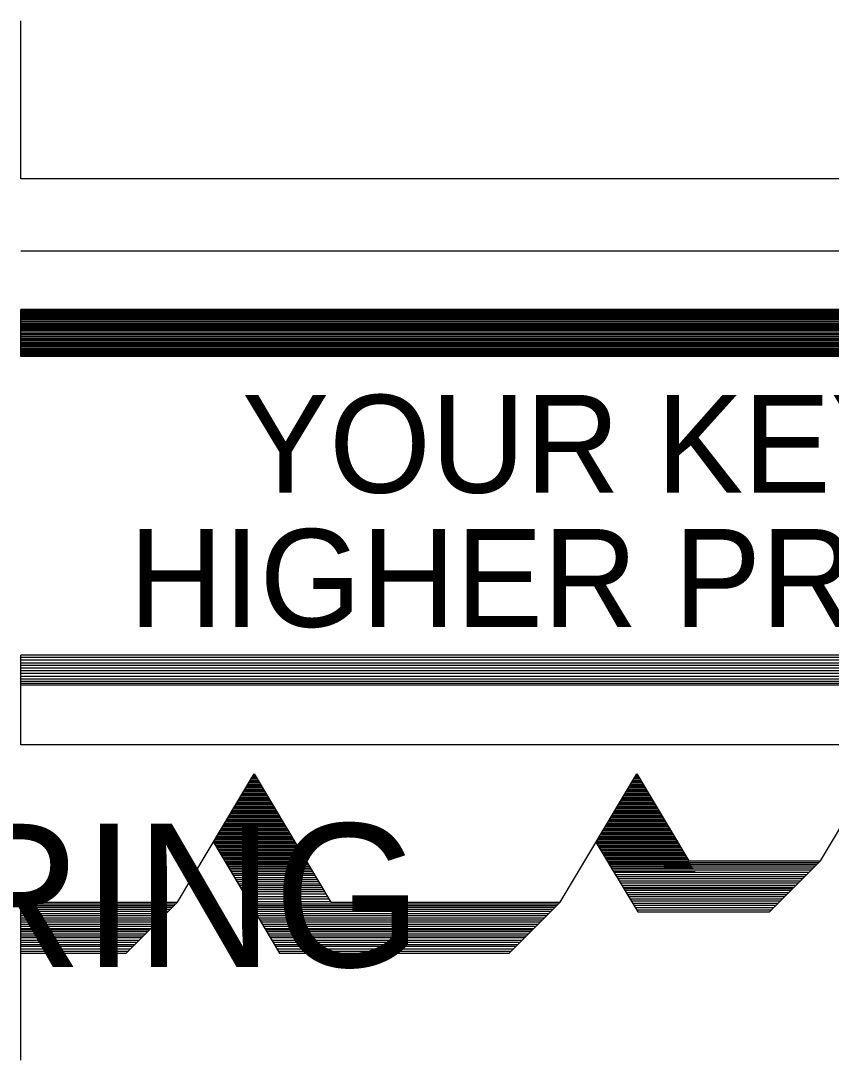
# Model space of a CAD drawing. Extents: x 22388.1 to 22405.7, y 22369.6 to 22390.4.
# Drawn here: x 22389.095 to 22389.2819, y 22369.983 to 22370.2226 of the extents above; entities that cross this region are included whole.
import ezdxf

# ---------------------------------------------------------------- set-up
doc = ezdxf.new("R2010")
doc.units = 0
for name, color, linetype in [('Level 1', 7, 'Continuous'), ('Level 10', 7, 'Continuous'), ('Level 2', 7, 'Continuous'), ('Level 7', 7, 'Continuous')]:
    doc.layers.add(name, color=color, linetype=linetype)

msp = doc.modelspace()

# ---------------------------------------------------------------- linework, layer by layer
at = {"layer": 'Level 1'}
msp.add_line((22389.095, 22370.1452), (22389.095, 22370.15608), dxfattribs=at)
at = {"layer": 'Level 10'}
msp.add_line((22389.4555, 22370.16949), (22389.095, 22370.16949), dxfattribs=at)
at = {"layer": 'Level 2'}
for p, q in [((22389.4717, 22370.15608), (22389.095, 22370.15608)), ((22389.47204, 22370.15583), (22389.095, 22370.15583)), ((22389.47233, 22370.15558), (22389.095, 22370.15558)), ((22389.47266, 22370.15529), (22389.095, 22370.15529)), ((22389.47304, 22370.15499), (22389.095, 22370.15499)), ((22389.47337, 22370.1547), (22389.095, 22370.1547)), ((22389.47379, 22370.15437), (22389.095, 22370.15437)), ((22389.47412, 22370.15408), (22389.095, 22370.15408)), ((22389.47454, 22370.15374), (22389.095, 22370.15374)), ((22389.47495, 22370.15341), (22389.095, 22370.15341)), ((22389.47529, 22370.15312), (22389.095, 22370.15312)), ((22389.47566, 22370.15279), (22389.095, 22370.15279)), ((22389.47612, 22370.15245), (22389.095, 22370.15245)), ((22389.47645, 22370.15216), (22389.095, 22370.15216)), ((22389.47679, 22370.15187), (22389.095, 22370.15187)), ((22389.4772, 22370.15154), (22389.095, 22370.15154)), ((22389.47762, 22370.1512), (22389.095, 22370.1512)), ((22389.478, 22370.15087), (22389.095, 22370.15087)), ((22389.47845, 22370.15049), (22389.095, 22370.15049)), ((22389.47883, 22370.1502), (22389.095, 22370.1502)), ((22389.4792, 22370.14987), (22389.095, 22370.14987)), ((22389.47966, 22370.14949), (22389.095, 22370.14949)), ((22389.48008, 22370.14916), (22389.095, 22370.14916)), ((22389.48037, 22370.14891), (22389.095, 22370.14891)), ((22389.48079, 22370.14858), (22389.095, 22370.14858)), ((22389.48116, 22370.14824), (22389.095, 22370.14824)), ((22389.48154, 22370.14795), (22389.095, 22370.14795)), ((22389.48187, 22370.14766), (22389.095, 22370.14766)), ((22389.4822, 22370.14741), (22389.095, 22370.14741)), ((22389.48266, 22370.14704), (22389.095, 22370.14704)), ((22389.48295, 22370.14679), (22389.095, 22370.14679)), ((22389.48329, 22370.14649), (22389.095, 22370.14649)), ((22389.48358, 22370.14624), (22389.095, 22370.14624)), ((22389.48391, 22370.14599), (22389.095, 22370.14599)), ((22389.48416, 22370.14579), (22389.095, 22370.14579)), ((22389.48445, 22370.14554), (22389.095, 22370.14554)), ((22389.48466, 22370.14537), (22389.095, 22370.14537)), ((22389.48487, 22370.1452), (22389.095, 22370.1452)), ((22389.50416, 22370.07637), (22389.095, 22370.07637)), ((22389.095, 22370.0557), (22389.095, 22370.07637)), ((22389.5035, 22370.07583), (22389.095, 22370.07583)), ((22389.50279, 22370.07524), (22389.095, 22370.07524)), ((22389.502, 22370.07458), (22389.095, 22370.07458)), ((22389.50133, 22370.07404), (22389.095, 22370.07404)), ((22389.50054, 22370.07337), (22389.095, 22370.07337)), ((22389.49983, 22370.07279), (22389.095, 22370.07279)), ((22389.49908, 22370.07216), (22389.095, 22370.07216)), ((22389.49825, 22370.07149), (22389.095, 22370.07149)), ((22389.4975, 22370.07087), (22389.095, 22370.07087)), ((22389.49679, 22370.07029), (22389.095, 22370.07029)), ((22389.49629, 22370.06987), (22389.095, 22370.06987)), ((22389.49583, 22370.06949), (22389.095, 22370.06949)), ((22389.47916, 22370.0557), (22389.095, 22370.0557)), ((22389.14758, 22370.04695), (22389.15008, 22370.04695)), ((22389.14779, 22370.04729), (22389.14987, 22370.04729)), ((22389.148, 22370.04762), (22389.14966, 22370.04762)), ((22389.14816, 22370.04795), (22389.1495, 22370.04795)), ((22389.14837, 22370.04829), (22389.14929, 22370.04829)), ((22389.14858, 22370.04862), (22389.14908, 22370.04862)), ((22389.23583, 22370.04695), (22389.23833, 22370.04695)), ((22389.23604, 22370.04729), (22389.23812, 22370.04729)), ((22389.23625, 22370.04762), (22389.23791, 22370.04762)), ((22389.23641, 22370.04795), (22389.23775, 22370.04795)), ((22389.23658, 22370.0482), (22389.23758, 22370.0482)), ((22389.23675, 22370.04845), (22389.23741, 22370.04845)), ((22389.23687, 22370.0487), (22389.23729, 22370.0487)), ((22389.14616, 22370.04462), (22389.15145, 22370.04462)), ((22389.14637, 22370.04495), (22389.15129, 22370.04495)), ((22389.14658, 22370.04529), (22389.15108, 22370.04529)), ((22389.14679, 22370.04562), (22389.15087, 22370.04562)), ((22389.147, 22370.04595), (22389.15066, 22370.04595)), ((22389.14716, 22370.04629), (22389.15045, 22370.04629)), ((22389.14737, 22370.04662), (22389.15029, 22370.04662)), ((22389.23441, 22370.04462), (22389.2397, 22370.04462)), ((22389.23462, 22370.04495), (22389.23954, 22370.04495)), ((22389.23483, 22370.04529), (22389.23933, 22370.04529)), ((22389.23504, 22370.04562), (22389.23912, 22370.04562)), ((22389.23525, 22370.04595), (22389.23891, 22370.04595)), ((22389.23541, 22370.04629), (22389.2387, 22370.04629)), ((22389.23562, 22370.04662), (22389.23854, 22370.04662)), ((22389.14479, 22370.04229), (22389.15287, 22370.04229)), ((22389.145, 22370.04262), (22389.15266, 22370.04262)), ((22389.1452, 22370.04295), (22389.15245, 22370.04295)), ((22389.14541, 22370.04329), (22389.15229, 22370.04329)), ((22389.14562, 22370.04362), (22389.15208, 22370.04362)), ((22389.14583, 22370.04395), (22389.15187, 22370.04395)), ((22389.14604, 22370.04429), (22389.15166, 22370.04429)), ((22389.23304, 22370.04229), (22389.24112, 22370.04229)), ((22389.23325, 22370.04262), (22389.24091, 22370.04262)), ((22389.23345, 22370.04295), (22389.2407, 22370.04295)), ((22389.23366, 22370.04329), (22389.24054, 22370.04329)), ((22389.23387, 22370.04362), (22389.24033, 22370.04362)), ((22389.23408, 22370.04395), (22389.24012, 22370.04395)), ((22389.23429, 22370.04429), (22389.23991, 22370.04429)), ((22389.1432, 22370.03962), (22389.15445, 22370.03962)), ((22389.14337, 22370.03995), (22389.15425, 22370.03995)), ((22389.14358, 22370.04029), (22389.15408, 22370.04029)), ((22389.14379, 22370.04062), (22389.15387, 22370.04062)), ((22389.144, 22370.04095), (22389.15366, 22370.04095)), ((22389.1442, 22370.04129), (22389.15345, 22370.04129)), ((22389.14437, 22370.04162), (22389.15325, 22370.04162)), ((22389.14458, 22370.04195), (22389.15308, 22370.04195)), ((22389.23145, 22370.03962), (22389.2427, 22370.03962)), ((22389.23162, 22370.03995), (22389.2425, 22370.03995)), ((22389.23183, 22370.04029), (22389.24233, 22370.04029)), ((22389.23204, 22370.04062), (22389.24212, 22370.04062)), ((22389.23225, 22370.04095), (22389.24191, 22370.04095)), ((22389.23245, 22370.04129), (22389.2417, 22370.04129)), ((22389.23262, 22370.04162), (22389.2415, 22370.04162)), ((22389.23283, 22370.04195), (22389.24133, 22370.04195)), ((22389.14183, 22370.03729), (22389.15587, 22370.03729)), ((22389.14204, 22370.03762), (22389.15566, 22370.03762)), ((22389.14225, 22370.03795), (22389.15545, 22370.03795)), ((22389.14245, 22370.03829), (22389.15525, 22370.03829)), ((22389.14266, 22370.03862), (22389.15508, 22370.03862)), ((22389.14279, 22370.03895), (22389.15487, 22370.03895)), ((22389.143, 22370.03929), (22389.15466, 22370.03929)), ((22389.23008, 22370.03729), (22389.24412, 22370.03729)), ((22389.23029, 22370.03762), (22389.24391, 22370.03762)), ((22389.2305, 22370.03795), (22389.2437, 22370.03795)), ((22389.2307, 22370.03829), (22389.2435, 22370.03829)), ((22389.23091, 22370.03862), (22389.24333, 22370.03862)), ((22389.23104, 22370.03895), (22389.24312, 22370.03895)), ((22389.23125, 22370.03929), (22389.24291, 22370.03929)), ((22389.14037, 22370.03495), (22389.15725, 22370.03495)), ((22389.14058, 22370.03529), (22389.15704, 22370.03529)), ((22389.14079, 22370.03562), (22389.15687, 22370.03562)), ((22389.141, 22370.03595), (22389.15666, 22370.03595)), ((22389.1412, 22370.03629), (22389.15645, 22370.03629)), ((22389.14141, 22370.03662), (22389.15625, 22370.03662)), ((22389.14162, 22370.03695), (22389.15604, 22370.03695)), ((22389.22862, 22370.03495), (22389.2455, 22370.03495)), ((22389.22883, 22370.03529), (22389.24529, 22370.03529)), ((22389.22904, 22370.03562), (22389.24512, 22370.03562)), ((22389.22925, 22370.03595), (22389.24491, 22370.03595)), ((22389.22945, 22370.03629), (22389.2447, 22370.03629)), ((22389.22966, 22370.03662), (22389.2445, 22370.03662)), ((22389.22987, 22370.03695), (22389.24429, 22370.03695)), ((22389.13941, 22370.03329), (22389.1547, 22370.0077)), ((22389.13941, 22370.03329), (22389.15825, 22370.03329)), ((22389.13958, 22370.03362), (22389.15804, 22370.03362)), ((22389.13962, 22370.03295), (22389.15845, 22370.03295)), ((22389.13979, 22370.03395), (22389.15783, 22370.03395)), ((22389.13983, 22370.03262), (22389.15866, 22370.03262)), ((22389.14, 22370.03429), (22389.15766, 22370.03429)), ((22389.1402, 22370.03462), (22389.15745, 22370.03462)), ((22389.22766, 22370.03329), (22389.23733, 22370.0172)), ((22389.22766, 22370.03329), (22389.2465, 22370.03329)), ((22389.22783, 22370.03362), (22389.24629, 22370.03362)), ((22389.22787, 22370.03295), (22389.2467, 22370.03295)), ((22389.22804, 22370.03395), (22389.24608, 22370.03395)), ((22389.22808, 22370.03262), (22389.24691, 22370.03262)), ((22389.22825, 22370.03429), (22389.24591, 22370.03429)), ((22389.22845, 22370.03462), (22389.2457, 22370.03462)), ((22389.14, 22370.03229), (22389.15883, 22370.03229)), ((22389.1402, 22370.03195), (22389.15904, 22370.03195)), ((22389.14041, 22370.03162), (22389.15916, 22370.03162)), ((22389.14062, 22370.03129), (22389.15937, 22370.03129)), ((22389.14079, 22370.03095), (22389.15958, 22370.03095)), ((22389.141, 22370.03062), (22389.15979, 22370.03062)), ((22389.1412, 22370.03029), (22389.16, 22370.03029)), ((22389.22825, 22370.03229), (22389.24708, 22370.03229)), ((22389.22845, 22370.03195), (22389.24729, 22370.03195)), ((22389.22866, 22370.03162), (22389.24741, 22370.03162)), ((22389.22887, 22370.03129), (22389.24762, 22370.03129)), ((22389.22904, 22370.03095), (22389.24783, 22370.03095)), ((22389.22925, 22370.03062), (22389.24804, 22370.03062)), ((22389.22945, 22370.03029), (22389.24825, 22370.03029)), ((22389.14141, 22370.02995), (22389.1602, 22370.02995)), ((22389.14162, 22370.02962), (22389.16041, 22370.02962)), ((22389.14179, 22370.02929), (22389.16062, 22370.02929)), ((22389.142, 22370.02895), (22389.16083, 22370.02895)), ((22389.1422, 22370.02862), (22389.16104, 22370.02862)), ((22389.14237, 22370.02837), (22389.1612, 22370.02837)), ((22389.14254, 22370.02804), (22389.16137, 22370.02804)), ((22389.14275, 22370.0277), (22389.16158, 22370.0277)), ((22389.22966, 22370.02995), (22389.24845, 22370.02995)), ((22389.22987, 22370.02962), (22389.24866, 22370.02962)), ((22389.23004, 22370.02929), (22389.24887, 22370.02929)), ((22389.23025, 22370.02895), (22389.24908, 22370.02895)), ((22389.23045, 22370.02862), (22389.24929, 22370.02862)), ((22389.23062, 22370.02837), (22389.24945, 22370.02837)), ((22389.23079, 22370.02804), (22389.24962, 22370.02804)), ((22389.231, 22370.0277), (22389.24983, 22370.0277)), ((22389.24333, 22370.02858), (22389.27904, 22370.02858)), ((22389.24333, 22370.0282), (22389.27866, 22370.0282)), ((22389.24333, 22370.02783), (22389.27829, 22370.02783)), ((22389.26766, 22370.0172), (22389.27945, 22370.02899)), ((22389.14295, 22370.02733), (22389.16183, 22370.02733)), ((22389.1432, 22370.02691), (22389.16208, 22370.02691)), ((22389.14345, 22370.02654), (22389.16229, 22370.02654)), ((22389.1437, 22370.02608), (22389.16258, 22370.02608)), ((22389.14395, 22370.02566), (22389.16279, 22370.02566)), ((22389.2312, 22370.02733), (22389.25008, 22370.02733)), ((22389.23145, 22370.02691), (22389.25033, 22370.02691)), ((22389.2317, 22370.02654), (22389.25054, 22370.02654)), ((22389.23183, 22370.02637), (22389.27683, 22370.02637)), ((22389.23212, 22370.02587), (22389.27633, 22370.02587)), ((22389.23241, 22370.02537), (22389.27583, 22370.02537)), ((22389.24333, 22370.02737), (22389.27783, 22370.02737)), ((22389.24333, 22370.02691), (22389.27737, 22370.02691)), ((22389.14429, 22370.02516), (22389.16312, 22370.02516)), ((22389.14454, 22370.0247), (22389.16337, 22370.0247)), ((22389.14483, 22370.0242), (22389.16366, 22370.0242)), ((22389.14512, 22370.0237), (22389.164, 22370.0237)), ((22389.14537, 22370.02329), (22389.16425, 22370.02329)), ((22389.14562, 22370.02287), (22389.1645, 22370.02287)), ((22389.2327, 22370.02491), (22389.27537, 22370.02491)), ((22389.233, 22370.02441), (22389.27487, 22370.02441)), ((22389.23329, 22370.02391), (22389.27437, 22370.02391)), ((22389.23358, 22370.02341), (22389.27387, 22370.02341)), ((22389.23391, 22370.02291), (22389.27337, 22370.02291)), ((22389.14595, 22370.02237), (22389.16479, 22370.02237)), ((22389.1462, 22370.02191), (22389.16504, 22370.02191)), ((22389.1465, 22370.02141), (22389.16533, 22370.02141)), ((22389.14691, 22370.02074), (22389.16575, 22370.02074)), ((22389.23408, 22370.02258), (22389.27304, 22370.02258)), ((22389.23433, 22370.0222), (22389.27266, 22370.0222)), ((22389.23462, 22370.0217), (22389.27216, 22370.0217)), ((22389.23491, 22370.0212), (22389.27166, 22370.0212)), ((22389.23516, 22370.02079), (22389.27125, 22370.02079)), ((22389.095, 22370.01908), (22389.1307, 22370.01908)), ((22389.095, 22370.0187), (22389.13033, 22370.0187)), ((22389.095, 22370.01833), (22389.12995, 22370.01833)), ((22389.11933, 22370.0077), (22389.13112, 22370.01949)), ((22389.14725, 22370.0202), (22389.16608, 22370.0202)), ((22389.14758, 22370.01962), (22389.16641, 22370.01962)), ((22389.14791, 22370.01908), (22389.219, 22370.01908)), ((22389.14812, 22370.0187), (22389.21862, 22370.0187)), ((22389.14837, 22370.01833), (22389.21825, 22370.01833)), ((22389.20762, 22370.0077), (22389.21941, 22370.01949)), ((22389.2355, 22370.02024), (22389.2707, 22370.02024)), ((22389.23579, 22370.01974), (22389.2702, 22370.01974)), ((22389.23612, 22370.01924), (22389.2697, 22370.01924)), ((22389.23637, 22370.01879), (22389.26925, 22370.01879)), ((22389.23675, 22370.0182), (22389.26866, 22370.0182)), ((22389.095, 22370.01787), (22389.1295, 22370.01787)), ((22389.095, 22370.01741), (22389.12904, 22370.01741)), ((22389.095, 22370.01687), (22389.1285, 22370.01687)), ((22389.095, 22370.01637), (22389.128, 22370.01637)), ((22389.095, 22370.01587), (22389.1275, 22370.01587)), ((22389.14862, 22370.01787), (22389.21779, 22370.01787)), ((22389.14891, 22370.01741), (22389.21733, 22370.01741)), ((22389.14925, 22370.01687), (22389.21679, 22370.01687)), ((22389.14954, 22370.01637), (22389.21629, 22370.01637)), ((22389.14983, 22370.01587), (22389.21579, 22370.01587)), ((22389.23704, 22370.0177), (22389.26816, 22370.0177)), ((22389.23733, 22370.0172), (22389.26766, 22370.0172)), ((22389.095, 22370.01541), (22389.12704, 22370.01541)), ((22389.095, 22370.01491), (22389.12654, 22370.01491)), ((22389.095, 22370.01441), (22389.12604, 22370.01441)), ((22389.095, 22370.01391), (22389.12554, 22370.01391)), ((22389.095, 22370.01341), (22389.12504, 22370.01341)), ((22389.15008, 22370.01541), (22389.21533, 22370.01541)), ((22389.15041, 22370.01491), (22389.21483, 22370.01491)), ((22389.1507, 22370.01441), (22389.21433, 22370.01441)), ((22389.151, 22370.01391), (22389.21383, 22370.01391)), ((22389.15129, 22370.01341), (22389.21333, 22370.01341)), ((22389.095, 22370.01308), (22389.1247, 22370.01308)), ((22389.095, 22370.0127), (22389.12433, 22370.0127)), ((22389.095, 22370.0122), (22389.12383, 22370.0122)), ((22389.095, 22370.0117), (22389.12333, 22370.0117)), ((22389.095, 22370.01129), (22389.12291, 22370.01129)), ((22389.1515, 22370.01308), (22389.213, 22370.01308)), ((22389.1517, 22370.0127), (22389.21262, 22370.0127)), ((22389.152, 22370.0122), (22389.21212, 22370.0122)), ((22389.15233, 22370.0117), (22389.21162, 22370.0117)), ((22389.15258, 22370.01129), (22389.2112, 22370.01129)), ((22389.095, 22370.01074), (22389.12237, 22370.01074)), ((22389.095, 22370.01024), (22389.12187, 22370.01024)), ((22389.095, 22370.00974), (22389.12137, 22370.00974)), ((22389.095, 22370.00929), (22389.12091, 22370.00929)), ((22389.095, 22370.0087), (22389.12033, 22370.0087)), ((22389.15287, 22370.01074), (22389.21066, 22370.01074)), ((22389.1532, 22370.01024), (22389.21016, 22370.01024)), ((22389.1535, 22370.00974), (22389.20966, 22370.00974)), ((22389.15375, 22370.00929), (22389.2092, 22370.00929)), ((22389.15412, 22370.0087), (22389.20862, 22370.0087)), ((22389.095, 22370.0082), (22389.11983, 22370.0082)), ((22389.095, 22370.0077), (22389.11933, 22370.0077)), ((22389.15441, 22370.0082), (22389.20812, 22370.0082)), ((22389.1547, 22370.0077), (22389.20762, 22370.0077))]:
    msp.add_line(p, q, dxfattribs=at)
at = {"layer": 'Level 7'}
for p, q in [((22389.095, 22370.18616), (22389.095, 22370.22262)), ((22389.43533, 22370.18616), (22389.095, 22370.18616)), ((22389.13112, 22370.01949), (22389.14883, 22370.04904)), ((22389.14883, 22370.04904), (22389.1665, 22370.01949)), ((22389.21941, 22370.01949), (22389.23708, 22370.04904)), ((22389.23708, 22370.04904), (22389.24912, 22370.02899)), ((22389.27945, 22370.02899), (22389.29145, 22370.04904)), ((22389.24912, 22370.02899), (22389.27945, 22370.02899)), ((22389.095, 22369.98304), (22389.095, 22370.01949)), ((22389.095, 22370.01949), (22389.13112, 22370.01949)), ((22389.1665, 22370.01949), (22389.21941, 22370.01949))]:
    msp.add_line(p, q, dxfattribs=at)

# ---------------------------------------------------------------- texts
at = {"layer": 'Level 2'}
for s, height, p in [('YOUR KEY TO', 0.0225623, (22389.146, 22370.11383)), ('HIGHER PROFITS', 0.0225623, (22389.11991, 22370.08291)), ('ENGINEERING', 0.0329975, (22388.8787, 22370.00454))]:
    msp.add_text(s, height=height, dxfattribs=at).set_placement(p)

doc.saveas('drawing.dxf')
